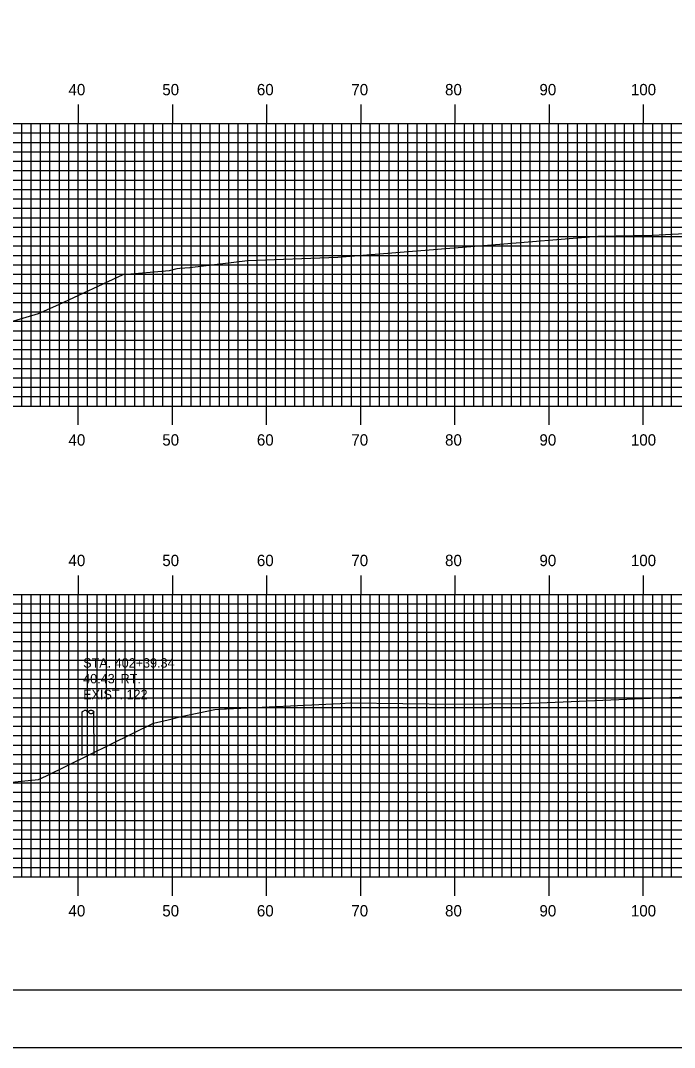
# Model space of a CAD drawing. Extents: x 850955 to 851298, y 364785 to 365005.
# Drawn here: x 851154.6 to 851224, y 364785.1 to 364894.2 of the extents above; entities that cross this region are included whole.
import ezdxf

# ---------------------------------------------------------------- set-up
doc = ezdxf.new("R2010")
doc.units = 0
for name, color, linetype in [('BORDER', 7, 'Continuous'), ('D_Text_Monospaced', 7, 'Continuous'), ('H_V ANNOTATION', 7, 'Continuous'), ('MAJOR', 7, 'Continuous'), ('MINOR', 7, 'Continuous'), ('PLOT BOUNDARY', 7, 'Continuous'), ('S_Roadway_Centerline', 7, 'Continuous'), ('S_Utilities_Pole_Power', 7, 'Continuous')]:
    doc.layers.add(name, color=color, linetype=linetype)

msp = doc.modelspace()

# ---------------------------------------------------------------- linework, layer by layer
at = {"layer": 'BORDER'}
msp.add_lwpolyline([(850971.08, 364791.23), (851291.08, 364791.23), (851291.08, 365001.23), (850971.08, 365001.23)], close=True, dxfattribs=at)
at = {"layer": 'MAJOR'}
for p, q in [((851160.68, 364885.24), (851160.68, 364883.23)), ((851170.68, 364885.24), (851170.68, 364883.23)), ((851180.68, 364885.24), (851180.68, 364883.23)), ((851190.68, 364885.24), (851190.68, 364883.23)), ((851200.68, 364885.24), (851200.68, 364883.23)), ((851210.68, 364885.24), (851210.68, 364883.23)), ((851220.68, 364885.24), (851220.68, 364883.23)), ((850980.68, 364883.23), (851260.68, 364883.23)), ((850980.68, 364883.23), (851260.68, 364883.23)), ((851160.68, 364853.23), (851160.68, 364883.23)), ((851170.68, 364853.23), (851170.68, 364883.23)), ((851180.68, 364853.23), (851180.68, 364883.23)), ((851190.68, 364853.23), (851190.68, 364883.23)), ((851200.68, 364853.23), (851200.68, 364883.23)), ((851210.68, 364853.23), (851210.68, 364883.23)), ((851220.68, 364853.23), (851220.68, 364883.23)), ((850980.68, 364878.23), (851260.68, 364878.23)), ((850980.68, 364873.23), (851260.68, 364873.23)), ((850980.68, 364868.23), (851260.68, 364868.23)), ((850980.68, 364863.23), (851260.68, 364863.23)), ((850980.68, 364858.23), (851260.68, 364858.23)), ((850980.68, 364853.23), (851260.68, 364853.23)), ((850980.68, 364853.23), (851260.68, 364853.23)), ((851160.68, 364851.23), (851160.68, 364853.23)), ((851170.68, 364851.23), (851170.68, 364853.23)), ((851180.68, 364851.23), (851180.68, 364853.23)), ((851190.68, 364851.23), (851190.68, 364853.23)), ((851200.68, 364851.23), (851200.68, 364853.23)), ((851210.68, 364851.23), (851210.68, 364853.23)), ((851220.68, 364851.23), (851220.68, 364853.23)), ((851160.68, 364835.24), (851160.68, 364833.23)), ((851170.68, 364835.24), (851170.68, 364833.23)), ((851180.68, 364835.24), (851180.68, 364833.23)), ((851190.68, 364835.24), (851190.68, 364833.23)), ((851200.68, 364835.24), (851200.68, 364833.23)), ((851210.68, 364835.24), (851210.68, 364833.23)), ((851220.68, 364835.24), (851220.68, 364833.23)), ((850980.68, 364833.23), (851260.68, 364833.23)), ((850980.68, 364833.23), (851260.68, 364833.23)), ((851160.68, 364803.23), (851160.68, 364833.23)), ((851170.68, 364803.23), (851170.68, 364833.23)), ((851180.68, 364803.23), (851180.68, 364833.23)), ((851190.68, 364803.23), (851190.68, 364833.23)), ((851200.68, 364803.23), (851200.68, 364833.23)), ((851210.68, 364803.23), (851210.68, 364833.23)), ((851220.68, 364803.23), (851220.68, 364833.23)), ((850980.68, 364828.23), (851260.68, 364828.23)), ((850980.68, 364823.23), (851260.68, 364823.23)), ((850980.68, 364818.23), (851260.68, 364818.23)), ((850980.68, 364813.23), (851260.68, 364813.23)), ((850980.68, 364808.23), (851260.68, 364808.23)), ((850980.68, 364803.23), (851260.68, 364803.23)), ((850980.68, 364803.23), (851260.68, 364803.23)), ((851160.68, 364801.23), (851160.68, 364803.23)), ((851170.68, 364801.23), (851170.68, 364803.23)), ((851180.68, 364801.23), (851180.68, 364803.23)), ((851190.68, 364801.23), (851190.68, 364803.23)), ((851200.68, 364801.23), (851200.68, 364803.23)), ((851210.68, 364801.23), (851210.68, 364803.23)), ((851220.68, 364801.23), (851220.68, 364803.23))]:
    msp.add_line(p, q, dxfattribs=at)
at = {"layer": 'MINOR'}
for p, q in [((851154.68, 364853.23), (851154.68, 364883.23)), ((851155.68, 364853.23), (851155.68, 364883.23)), ((851156.68, 364853.23), (851156.68, 364883.23)), ((851157.68, 364853.23), (851157.68, 364883.23)), ((851158.68, 364853.23), (851158.68, 364883.23)), ((851159.68, 364853.23), (851159.68, 364883.23)), ((851161.68, 364853.23), (851161.68, 364883.23)), ((851162.68, 364853.23), (851162.68, 364883.23)), ((851163.68, 364853.23), (851163.68, 364883.23)), ((851164.68, 364853.23), (851164.68, 364883.23)), ((851165.68, 364853.23), (851165.68, 364883.23)), ((851166.68, 364853.23), (851166.68, 364883.23)), ((851167.68, 364853.23), (851167.68, 364883.23)), ((851168.68, 364853.23), (851168.68, 364883.23)), ((851169.68, 364853.23), (851169.68, 364883.23)), ((851171.68, 364853.23), (851171.68, 364883.23)), ((851172.68, 364853.23), (851172.68, 364883.23)), ((851173.68, 364853.23), (851173.68, 364883.23)), ((851174.68, 364853.23), (851174.68, 364883.23)), ((851175.68, 364853.23), (851175.68, 364883.23)), ((851176.68, 364853.23), (851176.68, 364883.23)), ((851177.68, 364853.23), (851177.68, 364883.23)), ((851178.68, 364853.23), (851178.68, 364883.23)), ((851179.68, 364853.23), (851179.68, 364883.23)), ((851181.68, 364853.23), (851181.68, 364883.23)), ((851182.68, 364853.23), (851182.68, 364883.23)), ((851183.68, 364853.23), (851183.68, 364883.23)), ((851184.68, 364853.23), (851184.68, 364883.23)), ((851185.68, 364853.23), (851185.68, 364883.23)), ((851186.68, 364853.23), (851186.68, 364883.23)), ((851187.68, 364853.23), (851187.68, 364883.23)), ((851188.68, 364853.23), (851188.68, 364883.23)), ((851189.68, 364853.23), (851189.68, 364883.23)), ((851191.68, 364853.23), (851191.68, 364883.23)), ((851192.68, 364853.23), (851192.68, 364883.23)), ((851193.68, 364853.23), (851193.68, 364883.23)), ((851194.68, 364853.23), (851194.68, 364883.23)), ((851195.68, 364853.23), (851195.68, 364883.23)), ((851196.68, 364853.23), (851196.68, 364883.23)), ((851197.68, 364853.23), (851197.68, 364883.23)), ((851198.68, 364853.23), (851198.68, 364883.23)), ((851199.68, 364853.23), (851199.68, 364883.23)), ((851201.68, 364853.23), (851201.68, 364883.23)), ((851202.68, 364853.23), (851202.68, 364883.23)), ((851203.68, 364853.23), (851203.68, 364883.23)), ((851204.68, 364853.23), (851204.68, 364883.23)), ((851205.68, 364853.23), (851205.68, 364883.23)), ((851206.68, 364853.23), (851206.68, 364883.23)), ((851207.68, 364853.23), (851207.68, 364883.23)), ((851208.68, 364853.23), (851208.68, 364883.23)), ((851209.68, 364853.23), (851209.68, 364883.23)), ((851211.68, 364853.23), (851211.68, 364883.23)), ((851212.68, 364853.23), (851212.68, 364883.23)), ((851213.68, 364853.23), (851213.68, 364883.23)), ((851214.68, 364853.23), (851214.68, 364883.23)), ((851215.68, 364853.23), (851215.68, 364883.23)), ((851216.68, 364853.23), (851216.68, 364883.23)), ((851217.68, 364853.23), (851217.68, 364883.23)), ((851218.68, 364853.23), (851218.68, 364883.23)), ((851219.68, 364853.23), (851219.68, 364883.23)), ((851221.68, 364853.23), (851221.68, 364883.23)), ((851222.68, 364853.23), (851222.68, 364883.23)), ((851223.68, 364853.23), (851223.68, 364883.23)), ((850980.68, 364882.23), (851260.68, 364882.23)), ((850980.68, 364881.23), (851260.68, 364881.23)), ((850980.68, 364880.23), (851260.68, 364880.23)), ((850980.68, 364879.23), (851260.68, 364879.23)), ((850980.68, 364877.23), (851260.68, 364877.23)), ((850980.68, 364876.23), (851260.68, 364876.23)), ((850980.68, 364875.23), (851260.68, 364875.23)), ((850980.68, 364874.23), (851260.68, 364874.23)), ((850980.68, 364872.23), (851260.68, 364872.23)), ((850980.68, 364871.23), (851260.68, 364871.23)), ((850980.68, 364870.23), (851260.68, 364870.23)), ((850980.68, 364869.23), (851260.68, 364869.23)), ((850980.68, 364867.23), (851260.68, 364867.23)), ((850980.68, 364866.23), (851260.68, 364866.23)), ((850980.68, 364865.23), (851260.68, 364865.23)), ((850980.68, 364864.23), (851260.68, 364864.23)), ((850980.68, 364862.23), (851260.68, 364862.23)), ((850980.68, 364861.23), (851260.68, 364861.23)), ((850980.68, 364860.23), (851260.68, 364860.23)), ((850980.68, 364859.23), (851260.68, 364859.23)), ((850980.68, 364857.23), (851260.68, 364857.23)), ((850980.68, 364856.23), (851260.68, 364856.23)), ((850980.68, 364855.23), (851260.68, 364855.23)), ((850980.68, 364854.23), (851260.68, 364854.23)), ((851154.68, 364803.23), (851154.68, 364833.23)), ((851155.68, 364803.23), (851155.68, 364833.23)), ((851156.68, 364803.23), (851156.68, 364833.23)), ((851157.68, 364803.23), (851157.68, 364833.23)), ((851158.68, 364803.23), (851158.68, 364833.23)), ((851159.68, 364803.23), (851159.68, 364833.23)), ((851161.68, 364803.23), (851161.68, 364833.23)), ((851162.68, 364803.23), (851162.68, 364833.23)), ((851163.68, 364803.23), (851163.68, 364833.23)), ((851164.68, 364803.23), (851164.68, 364833.23)), ((851165.68, 364803.23), (851165.68, 364833.23)), ((851166.68, 364803.23), (851166.68, 364833.23)), ((851167.68, 364803.23), (851167.68, 364833.23)), ((851168.68, 364803.23), (851168.68, 364833.23)), ((851169.68, 364803.23), (851169.68, 364833.23)), ((851171.68, 364803.23), (851171.68, 364833.23)), ((851172.68, 364803.23), (851172.68, 364833.23)), ((851173.68, 364803.23), (851173.68, 364833.23)), ((851174.68, 364803.23), (851174.68, 364833.23)), ((851175.68, 364803.23), (851175.68, 364833.23)), ((851176.68, 364803.23), (851176.68, 364833.23)), ((851177.68, 364803.23), (851177.68, 364833.23)), ((851178.68, 364803.23), (851178.68, 364833.23)), ((851179.68, 364803.23), (851179.68, 364833.23)), ((851181.68, 364803.23), (851181.68, 364833.23)), ((851182.68, 364803.23), (851182.68, 364833.23)), ((851183.68, 364803.23), (851183.68, 364833.23)), ((851184.68, 364803.23), (851184.68, 364833.23)), ((851185.68, 364803.23), (851185.68, 364833.23)), ((851186.68, 364803.23), (851186.68, 364833.23)), ((851187.68, 364803.23), (851187.68, 364833.23)), ((851188.68, 364803.23), (851188.68, 364833.23)), ((851189.68, 364803.23), (851189.68, 364833.23)), ((851191.68, 364803.23), (851191.68, 364833.23)), ((851192.68, 364803.23), (851192.68, 364833.23)), ((851193.68, 364803.23), (851193.68, 364833.23)), ((851194.68, 364803.23), (851194.68, 364833.23)), ((851195.68, 364803.23), (851195.68, 364833.23)), ((851196.68, 364803.23), (851196.68, 364833.23)), ((851197.68, 364803.23), (851197.68, 364833.23)), ((851198.68, 364803.23), (851198.68, 364833.23)), ((851199.68, 364803.23), (851199.68, 364833.23)), ((851201.68, 364803.23), (851201.68, 364833.23)), ((851202.68, 364803.23), (851202.68, 364833.23)), ((851203.68, 364803.23), (851203.68, 364833.23)), ((851204.68, 364803.23), (851204.68, 364833.23)), ((851205.68, 364803.23), (851205.68, 364833.23)), ((851206.68, 364803.23), (851206.68, 364833.23)), ((851207.68, 364803.23), (851207.68, 364833.23)), ((851208.68, 364803.23), (851208.68, 364833.23)), ((851209.68, 364803.23), (851209.68, 364833.23)), ((851211.68, 364803.23), (851211.68, 364833.23)), ((851212.68, 364803.23), (851212.68, 364833.23)), ((851213.68, 364803.23), (851213.68, 364833.23)), ((851214.68, 364803.23), (851214.68, 364833.23)), ((851215.68, 364803.23), (851215.68, 364833.23)), ((851216.68, 364803.23), (851216.68, 364833.23)), ((851217.68, 364803.23), (851217.68, 364833.23)), ((851218.68, 364803.23), (851218.68, 364833.23)), ((851219.68, 364803.23), (851219.68, 364833.23)), ((851221.68, 364803.23), (851221.68, 364833.23)), ((851222.68, 364803.23), (851222.68, 364833.23)), ((851223.68, 364803.23), (851223.68, 364833.23)), ((850980.68, 364832.23), (851260.68, 364832.23)), ((850980.68, 364831.23), (851260.68, 364831.23)), ((850980.68, 364830.23), (851260.68, 364830.23)), ((850980.68, 364829.23), (851260.68, 364829.23)), ((850980.68, 364827.23), (851260.68, 364827.23)), ((850980.68, 364826.23), (851260.68, 364826.23)), ((850980.68, 364825.23), (851260.68, 364825.23)), ((850980.68, 364824.23), (851260.68, 364824.23)), ((850980.68, 364822.23), (851260.68, 364822.23)), ((850980.68, 364821.23), (851260.68, 364821.23)), ((850980.68, 364820.23), (851260.68, 364820.23)), ((850980.68, 364819.23), (851260.68, 364819.23)), ((850980.68, 364817.23), (851260.68, 364817.23)), ((850980.68, 364816.23), (851260.68, 364816.23)), ((850980.68, 364815.23), (851260.68, 364815.23)), ((850980.68, 364814.23), (851260.68, 364814.23)), ((850980.68, 364812.23), (851260.68, 364812.23)), ((850980.68, 364811.23), (851260.68, 364811.23)), ((850980.68, 364810.23), (851260.68, 364810.23)), ((850980.68, 364809.23), (851260.68, 364809.23)), ((850980.68, 364807.23), (851260.68, 364807.23)), ((850980.68, 364806.23), (851260.68, 364806.23)), ((850980.68, 364805.23), (851260.68, 364805.23)), ((850980.68, 364804.23), (851260.68, 364804.23))]:
    msp.add_line(p, q, dxfattribs=at)
at = {"layer": 'PLOT BOUNDARY'}
msp.add_lwpolyline([(850954.89, 364785.11), (851294.89, 364785.11), (851294.89, 365005.11), (850954.89, 365005.11)], close=True, dxfattribs=at)
at = {"layer": 'S_Roadway_Centerline'}
for points in [[(851152.54, 364861.87), (851156.45, 364863.05), (851158.61, 364864.02), (851165.44, 364867.21), (851170.38, 364867.63), (851171.19, 364867.84), (851171.46, 364867.88), (851172.54, 364867.95), (851178.66, 364868.69), (851188.25, 364869.03), (851204.56, 364870.34), (851215.86, 364871.28), (851221.64, 364871.38), (851233.42, 364871.99), (851234.52, 364872.04), (851235.61, 364872.1), (851252.93, 364873.86), (851260.68, 364873.78)], [(851151.37, 364813.08), (851156.48, 364813.57), (851157.32, 364813.95), (851168.69, 364819.56), (851170.22, 364819.9), (851171.62, 364820.26), (851175.19, 364821.01), (851176.2, 364821.08), (851176.44, 364821.08), (851188.48, 364821.65), (851189.58, 364821.7), (851200.72, 364821.58), (851207.97, 364821.64), (851221.43, 364822.19), (851226.53, 364822.38), (851236.9, 364822.87), (851245.22, 364823.33), (851248.75, 364823.82), (851256.88, 364824.07), (851260.68, 364824.28)]]:
    msp.add_lwpolyline(points, dxfattribs=at)
at = {"layer": 'S_Utilities_Pole_Power'}
for p, q in [((851161.11, 364816.12), (851161.1, 364820.74)), ((851161.11, 364820.74), (851161.26, 364820.85)), ((851161.57, 364820.85), (851161.73, 364820.74)), ((851161.89, 364820.85), (851161.73, 364820.74)), ((851161.73, 364820.74), (851161.89, 364820.63)), ((851162.36, 364820.74), (851162.2, 364820.85)), ((851162.2, 364820.63), (851162.36, 364820.74)), ((851162.36, 364816.12), (851162.35, 364820.74))]:
    msp.add_line(p, q, dxfattribs=at)
for centre, start, end in [((851161.42, 364820.63), 90, 125.2644), ((851161.42, 364820.63), 54.7356, 90), ((851162.04, 364820.63), 90, 125.2644), ((851162.04, 364820.63), 54.7356, 90), ((851162.04, 364820.85), 234.7356, 270), ((851162.04, 364820.85), 270, 305.2644)]:
    msp.add_arc(centre, 0.271, start, end, dxfattribs=at)

# ---------------------------------------------------------------- texts
at = {"layer": 'D_Text_Monospaced'}
for s, p in [('STA. 402+39.34', (851161.21, 364825.45)), ("40.43' RT.", (851161.21, 364823.78)), ('EXIST. 122', (851161.21, 364822.1))]:
    msp.add_text(s, height=1, dxfattribs=at).set_placement(p)
at = {"layer": 'H_V ANNOTATION'}
for s, p in [('40', (851159.65, 364886.23)), ('50', (851169.61, 364886.23)), ('60', (851179.65, 364886.23)), ('70', (851189.68, 364886.23)), ('80', (851199.63, 364886.23)), ('90', (851209.65, 364886.23)), ('100', (851219.36, 364886.23)), ('40', (851159.65, 364849.03)), ('50', (851169.61, 364849.03)), ('60', (851179.65, 364849.03)), ('70', (851189.68, 364849.03)), ('80', (851199.63, 364849.03)), ('90', (851209.65, 364849.03)), ('100', (851219.36, 364849.03)), ('40', (851159.65, 364836.23)), ('50', (851169.61, 364836.23)), ('60', (851179.65, 364836.23)), ('70', (851189.68, 364836.23)), ('80', (851199.63, 364836.23)), ('90', (851209.65, 364836.23)), ('100', (851219.36, 364836.23)), ('40', (851159.65, 364799.03)), ('50', (851169.61, 364799.03)), ('60', (851179.65, 364799.03)), ('70', (851189.68, 364799.03)), ('80', (851199.63, 364799.03)), ('90', (851209.65, 364799.03)), ('100', (851219.36, 364799.03))]:
    msp.add_text(s, height=1.2, dxfattribs=at).set_placement(p)

doc.saveas('drawing.dxf')
